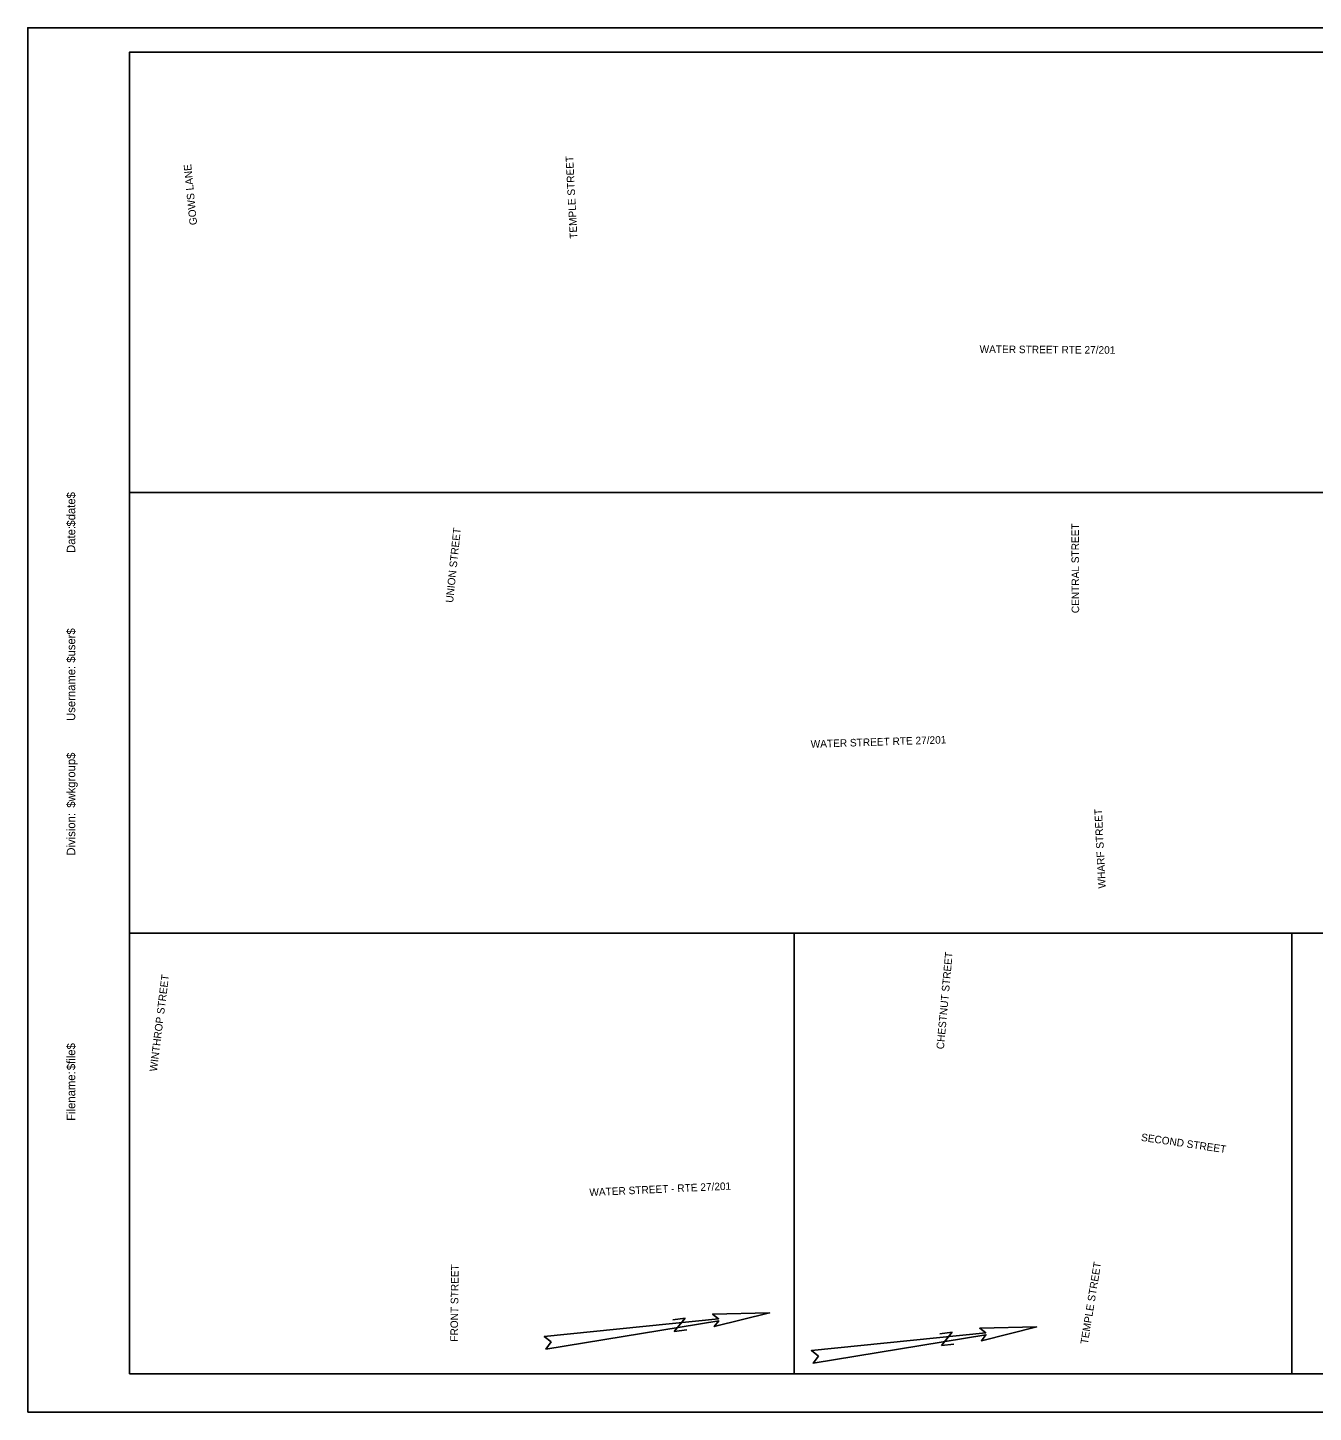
# Model space of a CAD drawing. Extents: x 0 to 850, y 0 to 550.
# Drawn here: x 0 to 511, y 0 to 550 of the extents above; entities that cross this region are included whole.
import ezdxf

# ---------------------------------------------------------------- set-up
doc = ezdxf.new("R2010")
doc.units = 0
for name, color, linetype in [('ANNOTATION', 7, 'Continuous'), ('BORDER', 7, 'Continuous'), ('D_Roadway_Centerline_Text', 7, 'Continuous'), ('Default', 7, 'Continuous'), ('H_V CONTROLS', 7, 'Continuous'), ('PLOT BOUNDARY', 7, 'Continuous')]:
    doc.layers.add(name, color=color, linetype=linetype)

msp = doc.modelspace()

# ---------------------------------------------------------------- linework, layer by layer
at = {"layer": 'BORDER'}
for p, q in [((840.33, 540.24), (40.33, 540.24)), ((40.33, 540.24), (40.33, 15.24)), ((40.33, 15.24), (840.33, 15.24))]:
    msp.add_line(p, q, dxfattribs=at)
at = {"layer": 'Default'}
for points in [[(40.33, 365.26), (790.33, 365.26), (790.33, 540.24), (40.33, 540.24)], [(40.33, 190.26), (789.25, 190.26), (789.25, 365.26), (40.33, 365.26)], [(40.33, 15.26), (304.5, 15.26), (304.5, 190.26), (40.33, 190.26)], [(304.5, 15.26), (502.28, 15.26), (502.28, 190.26), (304.5, 190.26)]]:
    msp.add_lwpolyline(points, close=True, dxfattribs=at)
at = {"layer": 'H_V CONTROLS'}
for p, q in [((294.68, 39.42), (272.05, 38.94)), ((274.42, 37.12), (272.05, 38.94)), ((294.68, 39.42), (272.7, 33.98)), ((274.42, 37.12), (205.13, 30.04)), ((274.52, 36.35), (205.79, 25.09)), ((274.52, 36.35), (272.7, 33.98)), ((400.84, 33.84), (378.21, 33.36)), ((380.58, 31.54), (378.21, 33.36)), ((400.84, 33.84), (378.86, 28.4)), ((207.94, 27.89), (205.13, 30.04)), ((207.94, 27.89), (205.79, 25.09)), ((380.58, 31.54), (311.29, 24.46)), ((380.68, 30.77), (311.95, 19.5)), ((380.68, 30.77), (378.86, 28.4)), ((314.1, 22.31), (311.29, 24.46)), ((314.1, 22.31), (311.95, 19.5))]:
    msp.add_line(p, q, dxfattribs=at)
for points in [[(207.94, 27.89), (205.79, 25.09), (274.52, 36.35), (272.7, 33.98), (294.68, 39.42), (272.05, 38.94), (274.42, 37.12), (205.13, 30.04), (207.94, 27.89)], [(256.2, 36.69), (261.16, 37.35)], [(261.16, 37.35), (256.83, 32.01)], [(314.1, 22.31), (311.95, 19.5), (380.68, 30.77), (378.86, 28.4), (400.84, 33.84), (378.21, 33.36), (380.58, 31.54), (311.29, 24.46), (314.1, 22.31)], [(256.83, 32.01), (261.78, 32.67)], [(362.36, 31.11), (367.32, 31.77)], [(367.32, 31.77), (362.99, 26.43)], [(362.99, 26.43), (367.94, 27.08)]]:
    msp.add_lwpolyline(points, dxfattribs=at)
at = {"layer": 'PLOT BOUNDARY'}
msp.add_lwpolyline([(-0.13, -0.05), (849.87, -0.05), (849.87, 549.95), (-0.13, 549.95)], close=True, dxfattribs=at)

# ---------------------------------------------------------------- texts
at = {"layer": 'ANNOTATION'}
msp.add_text('WHARF STREET', height=3, rotation=92.8597, dxfattribs=at).set_placement((428.31, 208.11))
at = {"layer": 'BORDER'}
for s, p in [('$date$', (18.76, 351.77)), ('Date:', (18.76, 341.33)), ('$user$', (18.76, 297.7)), ('Username:', (18.76, 274.58)), ('$wkgroup$', (18.76, 240.09)), ('Division:', (18.76, 221.08)), ('$file$', (18.76, 135.87)), ('Filename:', (18.76, 115.74))]:
    msp.add_text(s, height=3.348, rotation=90, dxfattribs=at).set_placement(p)
at = {"layer": 'D_Roadway_Centerline_Text'}
for s, rotation, p in [('GOWS LANE', 95.687, (67.23, 471.69)), ('TEMPLE STREET', 93.007, (218.34, 466.17)), ('WATER STREET RTE 27/201', 359.6018, (378.15, 420.78)), ('CENTRAL STREET', 90.1284, (417.72, 317.39)), ('UNION STREET', 83.9626, (168.9, 321.41)), ('WATER STREET RTE 27/201', 1.8745, (311.08, 263.89)), ('CHESTNUT STREET', 84.7686, (363.95, 144.07)), ('WINTHROP STREET', 82.8497, (51.23, 135.18)), ('SECOND STREET', 351.7014, (442.18, 107.8)), ('WATER STREET - RTE 27/201', 2.6177, (223.14, 85.82)), ('FRONT STREET', 89.3055, (170.8, 27.98)), ('TEMPLE STREET', 80.6279, (421.14, 26.83))]:
    msp.add_text(s, height=3, rotation=rotation, dxfattribs=at).set_placement(p)

doc.saveas('drawing.dxf')
